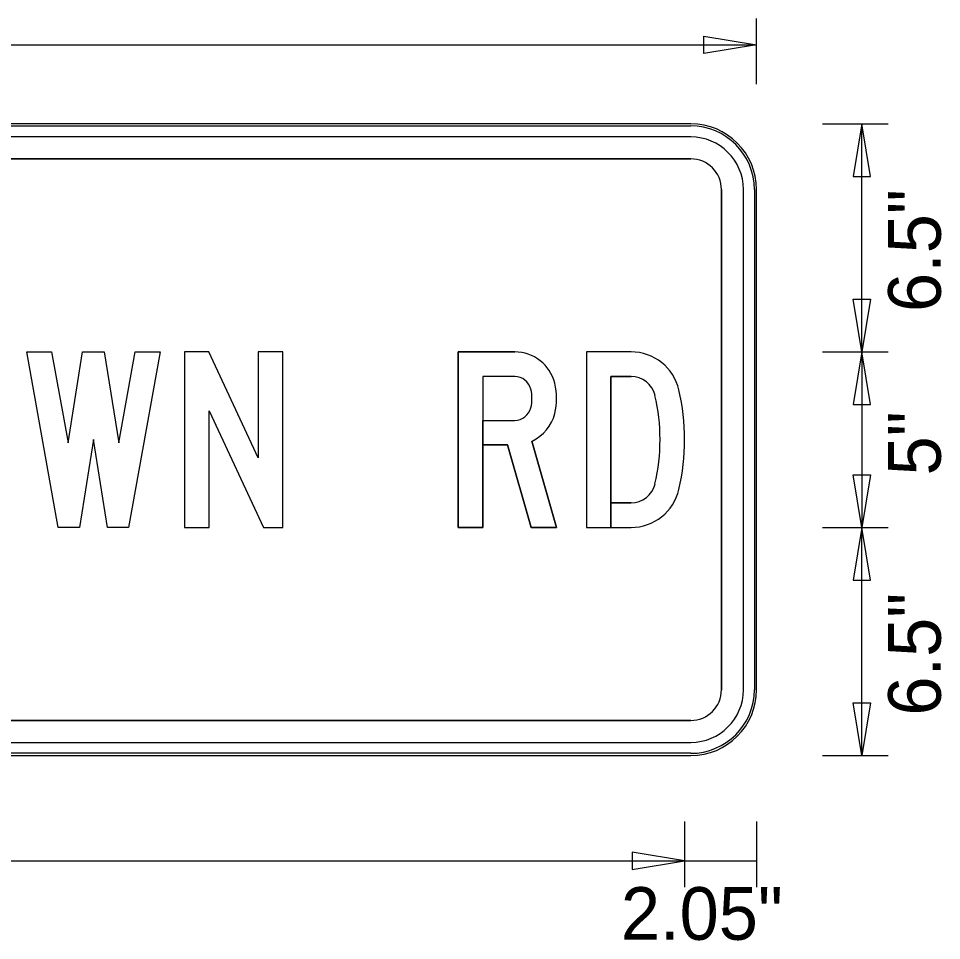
# Model space of a CAD drawing. Extents: x 1788.1 to 1851.2, y 237.2 to 283.4.
# Drawn here: x 1808.609 to 1811.24, y 250.141 to 252.768 of the extents above; entities that cross this region are included whole.
import ezdxf

# ---------------------------------------------------------------- set-up
doc = ezdxf.new("R2010")
doc.units = 0
for name, color, linetype in [('GSBWFILL', 7, 'Continuous'), ('GSCOLORFILL', 7, 'Continuous'), ('GSDIMS', 7, 'Continuous'), ('GSOUTLINE', 7, 'Continuous')]:
    doc.layers.add(name, color=color, linetype=linetype)

msp = doc.modelspace()

# ---------------------------------------------------------------- linework, layer by layer
at = {"layer": 'GSBWFILL'}
for p, q in [((1810.525, 252.4677), (1806.1, 252.4677)), ((1810.525, 252.4677), (1806.1, 252.4677)), ((1810.525, 252.4302), (1806.1, 252.4302)), ((1810.525, 252.4302), (1806.1, 252.4302)), ((1806.1, 252.3677), (1810.525, 252.3677)), ((1806.1, 252.3677), (1810.525, 252.3677)), ((1810.6125, 252.2802), (1810.6125, 250.8552)), ((1810.6125, 252.2802), (1810.6125, 250.8552)), ((1810.675, 250.8552), (1810.675, 252.2802)), ((1810.675, 250.8552), (1810.675, 252.2802)), ((1810.7125, 250.8552), (1810.7125, 252.2802)), ((1810.7125, 250.8552), (1810.7125, 252.2802)), ((1810.0232, 251.6227), (1810.0232, 251.6227)), ((1810.3549, 251.3877), (1810.2975, 251.3877)), ((1810.525, 250.7677), (1806.1006, 250.7677)), ((1810.525, 250.7677), (1806.1006, 250.7677)), ((1806.1006, 250.7052), (1810.525, 250.7052)), ((1806.1006, 250.7052), (1810.525, 250.7052)), ((1806.1, 250.6677), (1810.525, 250.6677)), ((1806.1, 250.6677), (1810.525, 250.6677))]:
    msp.add_line(p, q, dxfattribs=at)
for points in [[(1808.7502, 251.559), (1808.7916, 251.8177), (1808.8534, 251.8177), (1808.8948, 251.559), (1808.9414, 251.8177), (1809.0125, 251.8177), (1808.9225, 251.3177), (1808.8625, 251.3177), (1808.8225, 251.5677), (1808.7825, 251.3177), (1808.7225, 251.3177), (1808.6325, 251.8177), (1808.7036, 251.8177)], [(1809.3075, 251.3177), (1809.3625, 251.3177), (1809.3625, 251.8177), (1809.2925, 251.8177), (1809.2925, 251.5156), (1809.1516, 251.8177), (1809.0825, 251.8177), (1809.0825, 251.3177), (1809.1525, 251.3177), (1809.1525, 251.6502)]]:
    msp.add_lwpolyline(points, close=True, dxfattribs=at)
for points in [[(1810.0232, 251.7477), (1809.9325, 251.7477), (1809.9325, 251.3177), (1809.8625, 251.3177), (1809.8625, 251.8177), (1810.0232, 251.8177)], [(1810.3549, 251.8177), (1810.2275, 251.8177), (1810.2275, 251.3177), (1810.2975, 251.3177), (1810.2975, 251.7477), (1810.3549, 251.7477)], [(1810.0725, 251.5636), (1810.1425, 251.3177), (1810.0697, 251.3177), (1810.0028, 251.5527), (1809.9325, 251.5527), (1809.9325, 251.6227), (1810.0232, 251.6227)], [(1810.2975, 251.3877), (1810.2975, 251.3177), (1810.3549, 251.3177)]]:
    msp.add_lwpolyline(points, dxfattribs=at)
for centre, radius, start, end in [((1810.525, 252.2802), 0.1875, 0, 90), ((1810.525, 252.2802), 0.1875, 0, 90), ((1810.525, 252.2802), 0.15, 0, 90), ((1810.525, 252.2802), 0.15, 0, 90), ((1810.525, 252.2802), 0.0875, 0, 90), ((1810.525, 252.2802), 0.0875, 0, 90), ((1810.0232, 251.7002), 0.1175, 13.8865, 90), ((1810.3549, 251.6777), 0.14, 13.109, 90), ((1810.0232, 251.7002), 0.0475, 13.8865, 90), ((1809.9625, 251.6852), 0.18, 346.1135, 13.8865), ((1810.3549, 251.6777), 0.07, 13.109, 90), ((1809.9625, 251.6852), 0.11, 346.1135, 13.8865), ((1809.8825, 251.5677), 0.625, 346.891, 13.109), ((1809.8825, 251.5677), 0.555, 346.891, 13.109), ((1810.0232, 251.6702), 0.0475, 270, 346.1135), ((1810.0232, 251.6702), 0.1175, 294.8221, 346.1135), ((1810.3549, 251.4577), 0.07, 270, 346.891), ((1810.3549, 251.4577), 0.14, 270, 346.891), ((1810.525, 250.8552), 0.15, 270, 0), ((1810.525, 250.8552), 0.0875, 270, 0), ((1810.525, 250.8552), 0.1875, 270, 0), ((1810.525, 250.8552), 0.15, 270, 0), ((1810.525, 250.8552), 0.0875, 270, 0), ((1810.525, 250.8552), 0.1875, 270, 0)]:
    msp.add_arc(centre, radius, start, end, dxfattribs=at)
at = {"layer": 'GSCOLORFILL'}
for p, q in [((1810.525, 252.4677), (1806.1, 252.4677)), ((1810.525, 252.4677), (1806.1, 252.4677)), ((1810.525, 252.4677), (1806.1, 252.4677)), ((1810.525, 252.4677), (1806.1, 252.4677)), ((1806.1, 252.4615), (1810.525, 252.4615)), ((1806.1, 252.4615), (1810.525, 252.4615)), ((1810.525, 252.4302), (1806.1, 252.4302)), ((1810.525, 252.4302), (1806.1, 252.4302)), ((1806.1, 252.3677), (1810.525, 252.3677)), ((1806.1, 252.3677), (1810.525, 252.3677)), ((1810.6125, 252.2802), (1810.6125, 250.8552)), ((1810.6125, 252.2802), (1810.6125, 250.8552)), ((1810.675, 250.8552), (1810.675, 252.2802)), ((1810.675, 250.8552), (1810.675, 252.2802)), ((1810.7062, 252.2802), (1810.7062, 250.8552)), ((1810.7062, 252.2802), (1810.7062, 250.8552)), ((1810.7125, 250.8552), (1810.7125, 252.2802)), ((1810.7125, 250.8552), (1810.7125, 252.2802)), ((1810.7125, 250.8552), (1810.7125, 252.2802)), ((1810.7125, 250.8552), (1810.7125, 252.2802)), ((1810.0232, 251.6227), (1810.0232, 251.6227)), ((1810.3549, 251.3877), (1810.2975, 251.3877)), ((1810.525, 250.7677), (1806.1006, 250.7677)), ((1810.525, 250.7677), (1806.1006, 250.7677)), ((1806.1006, 250.7052), (1810.525, 250.7052)), ((1806.1006, 250.7052), (1810.525, 250.7052)), ((1810.525, 250.674), (1806.1001, 250.674)), ((1810.525, 250.674), (1806.1001, 250.674)), ((1806.1, 250.6677), (1810.525, 250.6677)), ((1806.1, 250.6677), (1810.525, 250.6677)), ((1806.1001, 250.6677), (1810.525, 250.6677)), ((1806.1001, 250.6677), (1810.525, 250.6677))]:
    msp.add_line(p, q, dxfattribs=at)
for points in [[(1808.7502, 251.559), (1808.7916, 251.8177), (1808.8534, 251.8177), (1808.8948, 251.559), (1808.9414, 251.8177), (1809.0125, 251.8177), (1808.9225, 251.3177), (1808.8625, 251.3177), (1808.8225, 251.5677), (1808.7825, 251.3177), (1808.7225, 251.3177), (1808.6325, 251.8177), (1808.7036, 251.8177)], [(1809.3075, 251.3177), (1809.3625, 251.3177), (1809.3625, 251.8177), (1809.2925, 251.8177), (1809.2925, 251.5156), (1809.1516, 251.8177), (1809.0825, 251.8177), (1809.0825, 251.3177), (1809.1525, 251.3177), (1809.1525, 251.6502)]]:
    msp.add_lwpolyline(points, close=True, dxfattribs=at)
for points in [[(1810.0232, 251.7477), (1809.9325, 251.7477), (1809.9325, 251.3177), (1809.8625, 251.3177), (1809.8625, 251.8177), (1810.0232, 251.8177)], [(1810.3549, 251.8177), (1810.2275, 251.8177), (1810.2275, 251.3177), (1810.2975, 251.3177), (1810.2975, 251.7477), (1810.3549, 251.7477)], [(1810.0725, 251.5636), (1810.1425, 251.3177), (1810.0697, 251.3177), (1810.0028, 251.5527), (1809.9325, 251.5527), (1809.9325, 251.6227), (1810.0232, 251.6227)], [(1810.2975, 251.3877), (1810.2975, 251.3177), (1810.3549, 251.3177)]]:
    msp.add_lwpolyline(points, dxfattribs=at)
for centre, radius, start, end in [((1810.525, 252.2802), 0.1875, 0, 90), ((1810.525, 252.2802), 0.1875, 0, 90), ((1810.525, 252.2802), 0.1875, 0, 90), ((1810.525, 252.2802), 0.1875, 0, 90), ((1810.525, 252.2802), 0.1812, 0, 90), ((1810.525, 252.2802), 0.1812, 0, 90), ((1810.525, 252.2802), 0.15, 0, 90), ((1810.525, 252.2802), 0.15, 0, 90), ((1810.525, 252.2802), 0.0875, 0, 90), ((1810.525, 252.2802), 0.0875, 0, 90), ((1810.0232, 251.7002), 0.1175, 13.8865, 90), ((1810.3549, 251.6777), 0.14, 13.109, 90), ((1810.0232, 251.7002), 0.0475, 13.8865, 90), ((1809.9625, 251.6852), 0.18, 346.1135, 13.8865), ((1810.3549, 251.6777), 0.07, 13.109, 90), ((1809.9625, 251.6852), 0.11, 346.1135, 13.8865), ((1809.8825, 251.5677), 0.625, 346.891, 13.109), ((1809.8825, 251.5677), 0.555, 346.891, 13.109), ((1810.0232, 251.6702), 0.0475, 270, 346.1135), ((1810.0232, 251.6702), 0.1175, 294.8221, 346.1135), ((1810.3549, 251.4577), 0.07, 270, 346.891), ((1810.3549, 251.4577), 0.14, 270, 346.891), ((1810.525, 250.8552), 0.1875, 270, 0), ((1810.525, 250.8552), 0.15, 270, 0), ((1810.525, 250.8552), 0.0875, 270, 0), ((1810.525, 250.8552), 0.1875, 270, 0), ((1810.525, 250.8552), 0.1812, 270, 0), ((1810.525, 250.8552), 0.1875, 270, 0), ((1810.525, 250.8552), 0.15, 270, 0), ((1810.525, 250.8552), 0.0875, 270, 0), ((1810.525, 250.8552), 0.1875, 270, 0), ((1810.525, 250.8552), 0.1812, 270, 0)]:
    msp.add_arc(centre, radius, start, end, dxfattribs=at)
at = {"layer": 'GSDIMS'}
for p, q in [((1810.7125, 252.5802), (1810.7125, 252.7677)), ((1805.9125, 252.6927), (1810.7125, 252.6927)), ((1810.7125, 252.5802), (1810.7125, 252.5802)), ((1810.9, 252.4677), (1811.0875, 252.4677)), ((1810.9, 252.4677), (1810.9, 252.4677)), ((1811.0125, 251.8177), (1811.0125, 252.4677)), ((1810.9, 251.8177), (1811.0875, 251.8177)), ((1810.9, 251.8177), (1811.0875, 251.8177)), ((1811.0125, 251.8177), (1811.0125, 251.3177)), ((1810.9, 251.3177), (1811.0875, 251.3177)), ((1810.9, 251.3177), (1811.0875, 251.3177)), ((1811.0125, 250.6677), (1811.0125, 251.3177)), ((1810.9, 250.6677), (1811.0875, 250.6677)), ((1810.9, 250.6677), (1810.9, 250.6677)), ((1810.5075, 250.4802), (1810.5075, 250.2927)), ((1810.5075, 250.4802), (1810.5075, 250.2927)), ((1810.7125, 250.4802), (1810.7125, 250.2927)), ((1810.7125, 250.4802), (1810.7125, 250.2927)), ((1806.1175, 250.3677), (1810.5075, 250.3677)), ((1810.5075, 250.3677), (1810.7125, 250.3677))]:
    msp.add_line(p, q, dxfattribs=at)
for points in [[(1810.7125, 252.6927), (1810.5625, 252.6677), (1810.5625, 252.7177)], [(1811.0125, 252.4677), (1810.9875, 252.3177), (1811.0375, 252.3177)], [(1811.0125, 251.8177), (1810.9875, 251.9677), (1811.0375, 251.9677)], [(1811.0125, 251.8177), (1810.9875, 251.6677), (1811.0375, 251.6677)], [(1811.0125, 251.3177), (1810.9875, 251.4677), (1811.0375, 251.4677)], [(1811.0125, 251.3177), (1810.9875, 251.1677), (1811.0375, 251.1677)], [(1811.0125, 250.6677), (1810.9875, 250.8177), (1811.0375, 250.8177)], [(1810.5075, 250.3677), (1810.3575, 250.3927), (1810.3575, 250.3427)]]:
    msp.add_lwpolyline(points, close=True, dxfattribs=at)
at = {"layer": 'GSOUTLINE'}
for p, q in [((1810.525, 252.4677), (1806.1, 252.4677)), ((1810.525, 252.4677), (1806.1, 252.4677)), ((1810.525, 252.4302), (1806.1, 252.4302)), ((1810.525, 252.4302), (1806.1, 252.4302)), ((1810.525, 252.3677), (1806.1, 252.3677)), ((1810.525, 252.3677), (1806.1, 252.3677)), ((1810.6125, 250.8552), (1810.6125, 252.2802)), ((1810.6125, 250.8552), (1810.6125, 252.2802)), ((1810.675, 250.8552), (1810.675, 252.2802)), ((1810.675, 250.8552), (1810.675, 252.2802)), ((1810.7125, 250.8552), (1810.7125, 252.2802)), ((1810.7125, 250.8552), (1810.7125, 252.2802)), ((1810.0232, 251.8177), (1809.8625, 251.8177)), ((1810.0232, 251.7477), (1810.0232, 251.7477)), ((1810.2975, 251.3877), (1810.3549, 251.3877)), ((1810.3549, 251.3177), (1810.3549, 251.3177)), ((1806.1, 250.7677), (1810.525, 250.7677)), ((1806.1, 250.7677), (1810.525, 250.7677)), ((1806.1, 250.7052), (1810.525, 250.7052)), ((1806.1, 250.7052), (1810.525, 250.7052)), ((1806.1, 250.6677), (1810.525, 250.6677)), ((1806.1, 250.6677), (1810.525, 250.6677))]:
    msp.add_line(p, q, dxfattribs=at)
for points in [[(1808.7502, 251.559), (1808.7916, 251.8177), (1808.8534, 251.8177), (1808.8948, 251.559), (1808.9414, 251.8177), (1809.0125, 251.8177), (1808.9225, 251.3177), (1808.8625, 251.3177), (1808.8225, 251.5677), (1808.7825, 251.3177), (1808.7225, 251.3177), (1808.6325, 251.8177), (1808.7036, 251.8177)], [(1809.3075, 251.3177), (1809.3625, 251.3177), (1809.3625, 251.8177), (1809.2925, 251.8177), (1809.2925, 251.5156), (1809.1516, 251.8177), (1809.0825, 251.8177), (1809.0825, 251.3177), (1809.1525, 251.3177), (1809.1525, 251.6502)]]:
    msp.add_lwpolyline(points, close=True, dxfattribs=at)
for points in [[(1809.8625, 251.8177), (1809.8625, 251.3177), (1809.9325, 251.3177), (1809.9325, 251.5527), (1810.0028, 251.5527), (1810.0697, 251.3177), (1810.1425, 251.3177), (1810.0725, 251.5636)], [(1810.3549, 251.8177), (1810.2275, 251.8177), (1810.2275, 251.3177), (1810.3549, 251.3177)], [(1810.0232, 251.7477), (1809.9325, 251.7477), (1809.9325, 251.6227), (1810.0232, 251.6227)], [(1810.3549, 251.7477), (1810.2975, 251.7477), (1810.2975, 251.3877)]]:
    msp.add_lwpolyline(points, dxfattribs=at)
for centre, radius, start, end in [((1810.525, 252.2802), 0.1875, 0, 90), ((1810.525, 252.2802), 0.1875, 0, 90), ((1810.525, 252.2802), 0.15, 0, 90), ((1810.525, 252.2802), 0.15, 0, 90), ((1810.525, 252.2802), 0.0875, 0, 90), ((1810.525, 252.2802), 0.0875, 0, 90), ((1810.0232, 251.7002), 0.1175, 13.8865, 90), ((1810.3549, 251.6777), 0.14, 13.109, 90), ((1810.0232, 251.7002), 0.0475, 13.8865, 90), ((1809.9625, 251.6852), 0.18, 346.1135, 13.8865), ((1810.3549, 251.6777), 0.07, 13.109, 90), ((1809.9625, 251.6852), 0.11, 346.1135, 13.8865), ((1809.8825, 251.5677), 0.625, 346.891, 13.109), ((1809.8825, 251.5677), 0.555, 346.891, 13.109), ((1810.0232, 251.6702), 0.0475, 270, 346.1135), ((1810.0232, 251.6702), 0.1175, 294.8221, 346.1135), ((1810.3549, 251.4577), 0.07, 270, 346.891), ((1810.3549, 251.4577), 0.14, 270, 346.891), ((1810.525, 250.8552), 0.15, 270, 0), ((1810.525, 250.8552), 0.0875, 270, 0), ((1810.525, 250.8552), 0.1875, 270, 0), ((1810.525, 250.8552), 0.15, 270, 0), ((1810.525, 250.8552), 0.0875, 270, 0), ((1810.525, 250.8552), 0.1875, 270, 0)]:
    msp.add_arc(centre, radius, start, end, dxfattribs=at)

# ---------------------------------------------------------------- texts
at = {"layer": 'GSDIMS'}
for s, p in [('6.5"', (1811.2375, 251.9314)), ('5"', (1811.2375, 251.4657)), ('6.5"', (1811.2375, 250.7814))]:
    msp.add_text(s, height=0.15, rotation=90, dxfattribs=at).set_placement(p)
msp.add_text('2.05"', height=0.15, dxfattribs=at).set_placement((1810.3259, 250.1427))

doc.saveas('drawing.dxf')
